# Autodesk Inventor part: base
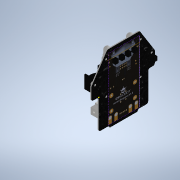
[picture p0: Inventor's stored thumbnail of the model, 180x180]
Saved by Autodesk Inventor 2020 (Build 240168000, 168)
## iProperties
Part Number: base
Material: Générique
Document SubType Name: Modeling
Designer: Buhl
Density: 1 g/cm^3
Appearance: Par défaut
Author: Buhl
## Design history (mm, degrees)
sketch "Esquisse1"
  geometry: L1 (0, 0)-(78, 0); L2 (78, -3)-(78, -44); L3 (14.627, -47)-(3, -47); L4 (0, -44)-(0, -3); L5 (-3, 0)-(-8.5, 0); L6 (-11.5, 3)-(-11.5, 19.102); L7 (-11.5, 20)-(88.5, 20); L8 (88.5, 19.135)-(88.5, 3); L9 (62.948, 58)-(15.117, 58); L10 (12.611, 56.649)-(-11.006, 20.75); L11 (88.04, 20.732)-(65.487, 56.597); L12 (81, 0)-(85.5, 0); L13 (18.5, -50)-(59.768, -50); L14 (75, -47)-(63.625, -47.035); A1 r 2 centre (86.5, 19.423) between (88.5, 19.423) and (88.193, 20.488); A2 r 2 centre (63.5, 56) between (65.193, 57.065) and (63.5, 58); A3 r 2 centre (14.578, 56) between (14.578, 58) and (12.907, 57.099); A4 r 2 centre (-9.5, 19.401) between (-11.171, 20.5) and (-11.5, 19.401); A5 r 2 centre (-9.5, 2) between (-11.5, 2) and (-9.5, 0); A6 r 3 centre (85.5, 19.135) between (88.5, 19.135) and (88.04, 20.732); A7 r 3 centre (62.948, 55) between (65.487, 56.597) and (62.948, 58); A8 r 3 centre (15.117, 55) between (15.117, 58) and (12.611, 56.649); A9 r 3 centre (-8.5, 19.102) between (-11.006, 20.75) and (-11.5, 19.102); A10 r 3 centre (-8.5, 3) between (-11.5, 3) and (-8.5, 0); A11 r 3 centre (-3, -3) between (0, -3) and (-3, 0); A12 r 3 centre (3, -44) between (0, -44) and (3, -47); A13 r 3 centre (75, -44) between (75, -47) and (78, -44); A14 r 3 centre (81, -3) between (81, 0) and (78, -3); A15 r 3 centre (85.5, 3) between (85.5, 0) and (88.5, 3); A16 r 2 centre (14.627, -49) between (16.564, -48.5) and (14.627, -47); A17 r 2 centre (63.632, -49.035) between (63.625, -47.035) and (61.7, -48.518); A18 r 2 centre (18.5, -48) between (16.564, -48.5) and (18.5, -50); A19 r 2 centre (59.768, -48) between (59.768, -50) and (61.7, -48.518); 8 further points
  constraints: 38 point on circle, 36 tangent, 33 point on line, 28 end point, 19 centre point, 14 equal radius, 4 horizontal, 4 parallel, 2 perpendicular
  dimensions: "d0" = 78 distance of point (78, -47) point (0, -47); "d1" = 47 distance of L1.end point (78, -47); "d2" = 100 distance of L7.start L7.end; "d3" = 11.5 distance between parallel lines of L6 L4; "d4" = 20 distance of point (-11.5, 0) L7.start; "d5" = 105 distance between parallel lines of L3 L9; "d6" = 50 distance of point (63.5, 58) point (13.5, 58); "d7" = 25 distance from line of point (13.5, 58) L6; "d8" = 2 radius of A1 (derived); "d9" = 3 radius of A6; "d10" = 3 radius of A14 (derived); "d247" = 3 distance between parallel lines of L3 L13; "d249" = 2 radius of A16 (derived)
extrude "Extrusion1" new body sketch "Esquisse1" distance "d11" = 1.6; taper "d12" = 0 deg
sketch "Esquisse2"
  geometry: L1 (-47, 3)-(-47, 75) reference; L2 (-44, 78)-(-3, 78) reference; L3 (-47, 3)-(-47, 75) reference; L4 (-47, 39)-(32.996, 39); L5 (-50, 18.5)-(-50, 59.768) reference; L6 (0, 81)-(0, 85.5) reference; L7 (3, 88.5)-(19.135, 88.5) reference; L8 (58, 62.948)-(58, 15.117) reference; L9 (20.732, 88.04)-(56.597, 65.487) reference; C1 r 1.5 at (19.402, 83.5); C2 r 1.5 at (46, 66.244); C3 r 1.5 at (-3, 66); C4 r 1.5 at (-32, 39); 3 further points
  constraints: 4 centre point, 2 end point, 1 horizontal, 1 midpoint, 1 point on line
  dimensions: "d13" = 3 diameter of C1; "d16" = 3 diameter of C2; "d18" = 3 diameter of C3; "d255" = 3 diameter of C4; "d256" = 18 distance from line of L5 C4.centre; "d257" = 12 distance from line of L2 C3.centre; "d258" = 3 distance from line of C3.centre L6; "d259" = 5 distance from line of L7 C1.centre; "d260" = 12 distance from line of L8 C2.centre; "d261" = 5 distance from line of L9 C2.centre; "d295" = 29 horizontal distance of C4.centre C3.centre (derived)
extrude "Extrusion2" cut sketch "Esquisse2" distance "d21" = 1.6; taper "d22" = 0 deg
sketch "Esquisse3"
  geometry: C1 r 1.5 at (-3, 66) reference; C2 r 1.5 at (46, 66.244) reference; C3 r 1.5 at (19.402, 83.5) reference; C4 r 2.75 at (-3, 66); C5 r 2.75 at (46, 66.244); C6 r 1.5 at (19.402, 83.5) reference; C7 r 2.75 at (19.402, 83.5); C8 r 1.5 at (-32, 39) reference; C9 r 2.75 at (-32, 39); 1 further point
  constraints: 4 centre point, 4 coincident
  dimensions: "d23" = 5.5 diameter of C4; "d24" = 5.5 diameter of C5; "d25" = 5.5 diameter of C7; "d262" = 5.5 diameter of C9
extrude "Extrusion3" join sketch "Esquisse3" distance "d26" = 3; taper "d27" = 0 deg
sketch "Esquisse4"
  geometry: L1 (-26, 10.532)-(-32, 10.532); L2 (-32, 10.532)-(-32, 67.532); L3 (-32, 67.532)-(-26, 67.532); L4 (-26, 67.532)-(-26, 10.532); L5 (-58, 62.948)-(-58, 15.117) reference; L6 (-3.465, 3.627)-(-1.465, 3.627); L7 (-1.465, 3.627)-(-1.465, 54.627); L8 (-1.465, 54.627)-(-3.465, 54.627); L9 (-3.465, 54.627)-(-3.465, 3.627); L10 (-58, 39.032)-(-14.636, 39.032); 2 further points
  constraints: 18 end point, 4 parallel, 3 horizontal, 2 midpoint, 2 perpendicular, 1 point on line
  dimensions: "d28" = 32 distance between parallel lines of L4 L5; "d29" = 6 distance of L2.end L3.end; "d30" = 51 distance of L8.end L6.start; "d31" = 57 distance between parallel lines of L3 L1; "d32" = 2 distance between parallel lines of L7 L9
extrude "Extrusion4" join sketch "Esquisse4" distance "d33" = 12.2; taper "d34" = 0 deg
sketch "Esquisse5"
  geometry: 1 further point
sketch "Esquisse6"
  geometry: 1 further point
node "Plan de construction1"
node "Plan de construction3"
mirror "Symétrie1"
sketch "Esquisse9"
  geometry: L1 (-3, 0)-(-44, 0) reference; L2 (-32, 0)-(-17, 0); L3 (-17, 0)-(-17, 24); L4 (-17, 24)-(-32, 24); L5 (-32, 24)-(-32, 0); L6 (-47, 3)-(-47, 75) reference; 1 further point
  constraints: 8 end point, 2 parallel, 1 horizontal, 1 perpendicular, 1 point on line
  dimensions: "d54" = 15 distance of L4.end L3.end; "d55" = 24 distance of L3.end L2.end; "d56" = 15 distance between parallel lines of L6 L5
extrude "Extrusion8" join sketch "Esquisse9" distance "d57" = 11; taper "d58" = 0 deg
sketch "Esquisse10"
  geometry: L1 (0, 12)-(-11, 12) reference; L2 (0, 12)-(0, 27) reference; L3 (-11, 12)-(0, 27); C1 r 1.5 at (-5.5, 19.5); 1 further point
  constraints: 2 end point, 1 centre point, 1 midpoint
  dimensions: "d59" = 3 diameter of C1
extrude "Extrusion9" cut sketch "Esquisse10" distance "d60" = 10; taper "d61" = 0 deg
sketch "Esquisse11"
  geometry: L1 (-36, 41.532)-(-42, 41.532); L2 (-42, 41.532)-(-42, 46.532); L3 (-42, 46.532)-(-36, 46.532); L4 (-36, 46.532)-(-36, 41.532); L5 (-58, 62.948)-(-58, 15.117) reference; L6 (-15, 82.5)-(-9, 82.5); L7 (-9, 82.5)-(-9, 87.5); L8 (-9, 87.5)-(-15, 87.5); L9 (-15, 87.5)-(-15, 82.5); L10 (0, 81)-(0, 85.5) reference; L11 (-3, 88.5)-(-19.135, 88.5) reference; L12 (-61.191, 39.032)-(-11.173, 39.032); L13 (-42, 51.532)-(-36, 51.532); L14 (-36, 51.532)-(-36, 56.532); L15 (-36, 56.532)-(-42, 56.532); L16 (-42, 56.532)-(-42, 51.532); 2 further points
  constraints: 26 end point, 6 parallel, 4 horizontal, 3 perpendicular, 1 midpoint, 1 point on line
  dimensions: "d63" = 5 distance of L1.end L2.end; "d64" = 6 distance of L2.end L3.end; "d65" = 22 distance between parallel lines of L4 L5; "d271" = 6 distance of L7.end L8.end; "d272" = 5 distance of L6.end L7.end; "d273" = 9 distance between parallel lines of L10 L7; "d274" = 6 distance between parallel lines of L11 L6; "d275" = 2.5 distance between parallel lines of L1 L12; "d276" = 6 distance of L15.end L14.end; "d277" = 5 distance of L14.end L13.end; "d278" = 5 distance between parallel lines of L13 L3
extrude "Extrusion10" join sketch "Esquisse11" distance "d66" = 5; taper "d67" = 0 deg
mirror "Symétrie3"
sketch "Esquisse13"
  geometry: L1 (-52.453, 14.685)-(-52.453, 64.242); L2 (-52.453, 64.242)-(45.75, 64.242); L3 (45.75, 64.242)-(45.75, 14.685); L4 (45.75, 14.685)-(-52.453, 14.685); 1 further point; 1 other entity
  constraints: 2 other
  node "Image1"
sketch "Esquisse14"
  geometry: L1 (42.128, 71.823)-(42.128, 5.773); L2 (42.128, 5.773)-(-45.058, 5.773); L3 (-45.058, 5.773)-(-45.058, 71.823); L4 (-45.058, 71.823)-(42.128, 71.823); 1 further point; 1 other entity
  constraints: 2 end point, 1 other
  node "Image2"
sketch "Esquisse16"
  geometry: L1 (-32, 24)-(-32, 0) reference; L2 (-32, 0)-(-17, 0) reference; L3 (-32, 0)-(-29.5, 0); L4 (-29.5, 0)-(-29.5, 7); L5 (-29.5, 7)-(-32, 7); L6 (-32, 7)-(-32, 0); L7 (-17, 0)-(-19.5, 0); L8 (-19.5, 0)-(-19.5, 7); L9 (-19.5, 7)-(-17, 7); L10 (-17, 7)-(-17, 0); L11 (-32, 54)-(-32, 78) reference; L12 (-32, 78)-(-17, 78) reference; L13 (-17, 78)-(-17, 54) reference; L14 (-32, 78)-(-29.5, 78); L15 (-29.5, 78)-(-29.5, 71); L16 (-29.5, 71)-(-32, 71); L17 (-32, 71)-(-32, 78); L18 (-17, 78)-(-19.5, 78); L19 (-19.5, 78)-(-19.5, 71); L20 (-19.5, 71)-(-17, 71); L21 (-17, 71)-(-17, 78); 1 further point
  constraints: 32 end point, 8 parallel, 4 horizontal, 4 perpendicular, 2 point on line
  dimensions: "d186" = 2.5 distance of L4.end L5.end; "d187" = 2.5 distance of L8.end L9.end; "d188" = 7 distance of L3.end L4.end; "d189" = 7 distance of L18.end L19.end
extrude "Extrusion13" cut sketch "Esquisse16" distance "d190" = 11; taper "d191" = 0 deg
node "Plan de construction2"
sketch "Esquisse12"
  geometry: C1 r 1.683 at (-14.287, 36.5); C2 r 1.703 at (-9.745, 36.5); 1 further point
  constraints: 2 centre point
extrude "Extrusion11" cut sketch "Esquisse12" distance "d68" = 0.5; taper "d69" = 0 deg
mirror "Symétrie2"
sketch "Esquisse17"
  geometry: L1 (-44, 78)-(-3, 78) reference; L2 (-3, 0)-(-44, 0) reference; L3 (0, 78)-(20, 78); L4 (20, 78)-(20, 0); L5 (20, 0)-(0, 0); L6 (0, 0)-(0, 78); 3 further points
  constraints: 8 end point, 2 parallel, 1 horizontal, 1 perpendicular
  dimensions: "d222" = 20 distance of L4.end L5.end
extrude "Extrusion14" join sketch "Esquisse17" distance "d223" = 21; taper "d224" = 0 deg
sketch "Esquisse18"
  geometry: L1 (0, 0)-(0, 78) reference; L2 (0, 0)-(21, 0) reference; L3 (21, 78)-(21, 0) reference; L4 (0, 78)-(21, 78) reference; L5 (22.117, 76.165)-(15.78, 76.165); L6 (15.78, 1.988)-(22.117, 1.988); L7 (22.117, 1.988)-(22.117, 76.165); L8 (0, 24)-(11, 24) reference; L9 (8.573, 52.434)-(8.573, 24); L10 (8.573, 24)-(13.171, 24); L11 (13.171, 52.434)-(13.171, 64.289); L12 (13.171, 64.289)-(15.78, 69.704); L13 (13.171, 24)-(13.171, 13.419); L14 (13.171, 13.419)-(15.78, 7.082); L15 (15.78, 76.165)-(15.78, 69.704); L16 (15.78, 7.082)-(15.78, 1.988); L17 (13.171, 52.434)-(8.573, 52.434); 2 further points
  constraints: 24 end point, 4 parallel, 3 perpendicular, 2 horizontal, 2 point on line, 1 vertical
extrude "Extrusion15" cut sketch "Esquisse18" distance "d265" = 20; taper "d266" = 0 deg
sketch "Esquisse19"
  geometry: L1 (21, 20)-(0, 20) reference; L2 (0, 20)-(21, 0); L3 (0, 0)-(21, 20); C1 r 9.355 at (9.339, 10)
  constraints: 4 end point, 1 centre point
extrude "Extrusion16" cut sketch "Esquisse19" stored distance "d267" = 20; taper "d268" = 0 deg
sketch "Esquisse20"
  geometry: L1 (30.205, 66.59)-(27.421, 66.59); L2 (27.421, 66.59)-(27.421, 11.814); L3 (27.421, 11.814)-(30.205, 11.814); L4 (30.205, 11.814)-(30.205, 66.59); 1 further point
  constraints: 8 end point, 2 parallel, 1 horizontal, 1 perpendicular
extrude "Extrusion17" cut sketch "Esquisse20" distance "d269" = 10; taper "d270" = 0 deg
mirror "Symétrie4"
node "Plan de construction5"
sketch "Esquisse22"
  geometry: L1 (0, -26.617)-(1.6, -26.617) reference; L2 (0, 73.383)-(1.6, 73.383) reference; C1 r 5 at (-5.411, 5.383); C2 r 5 at (-5.411, 41.383); 1 further point
  constraints: 2 centre point
  dimensions: "d280" = 10 diameter of C1; "d281" = 10 diameter of C2; "d282" = 32 distance from line of L1 C1.centre; "d283" = 32 distance from line of C2.centre L2
extrude "Extrusion18" join sketch "Esquisse22" distance "d284" = 2; taper "d285" = 0 deg
sketch "Esquisse23"
  geometry: C1 r 4.5 at (0, 0); C2 r 5 at (0, 36) reference; C3 r 4.5 at (0, 36); 1 further point
  constraints: 2 centre point, 1 coincident
  dimensions: "d286" = 9 diameter of C1; "d287" = 9 diameter of C3
extrude "Extrusion19" join sketch "Esquisse23" distance "d288" = 11; taper "d289" = 0 deg
fillet "Congé1" dims "d290" = 4.5
node "Solide1"
node "Boucle projetée4"
node "Plan de construction4"
node "Boucle projetée5"
other parameters: "d35" = -39, "d231" = -39, "d279" = -15
